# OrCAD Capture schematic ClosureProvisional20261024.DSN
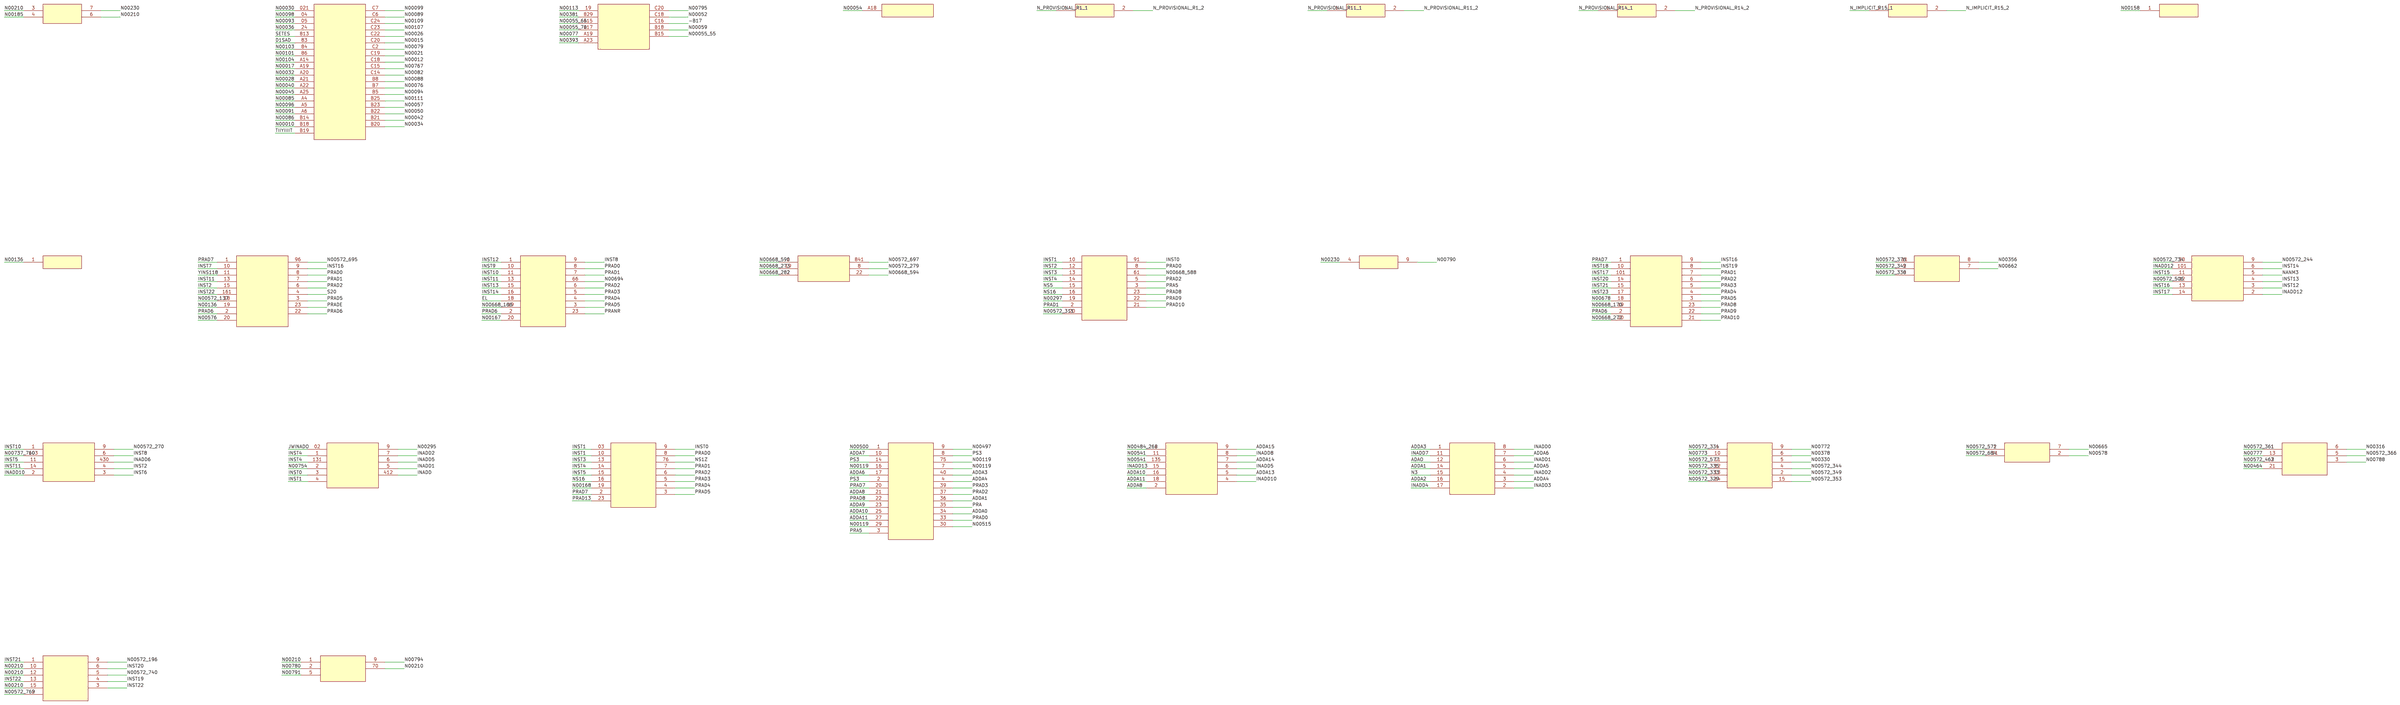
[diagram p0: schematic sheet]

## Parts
J1  CONNECTOR
P1  CONNECTOR
P2  CONNECTOR
P3  CONNECTOR
R1  1K00
R11  1K00
R14  1K00
R15  1K00
R18  330R
R20  510R
U1  UNKNOWN
U2  UNKNOWN
U3  UNKNOWN
U13  UNKNOWN
U14  UNKNOWN
U15  UNKNOWN
U19  74F02
U25  74F240
U27  74F174
U28  74F174
U29  74F174
U31  AM291C
U33  74F240
U34  74F240
U38  74F151
U39  74F00
U40  74F103
U_1  74F174
U_2  74F00

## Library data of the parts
J1 = OBS_J1
P1 = OBS_P1
P2 = OBS_P2
P3 = OBS_P3
R1 = OBS_R1
R11 = OBS_R11
R14 = OBS_R14
R15 = OBS_R15
R18 = OBS_R18
R20 = OBS_R20
U1 = OBS_U1
U2 = OBS_U2
U3 = OBS_U3
U13 = OBS_U13
U14 = OBS_U14
U15 = OBS_U15
U19 = OBS_U19
U25 = OBS_U25
U27 = OBS_U27
U28 = OBS_U28
U29 = OBS_U29
U31 = OBS_U31
U33 = OBS_U33
U34 = OBS_U34
U38 = OBS_U38
U39 = OBS_U39
U40 = OBS_U40
U_1 = OBS_U_1
U_2 = OBS_U_2

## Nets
-B17: P2.C16
ADAO: U34.12
ADDA0: U31.34
ADDA1: U31.36 U34.14
ADDA2: U34.16
ADDA3: U31.40 U34.1
ADDA4: U31.4 U34.3
ADDA5: U34.5
ADDA6: U31.17 U34.7
ADDA7: U31.10
ADDA8: U31.21 U33.2
ADDA9: U31.23
ADDA10: U31.25 U33.16
ADDA11: U31.27 U33.18
ADDA13: U33.5
ADDA14: U33.7
ADDA15: U33.9
D1SAD: P1.83
EL: U13.18
INADD: U29.412
INADD0: U34.8
INADD1: U29.5 U34.6
INADD2: U29.7 U34.4
INADD3: U34.2
INADD4: U34.17
INADD5: U29.6 U33.6
INADD6: U28.430
INADD7: U34.11
INADD8: U33.8
INADD10: U28.2 U33.4
INADD12: U27.2 U27.101
INADD13: U33.15
INST0: U3.9 U15.91 U29.3
INST1: U3.03 U3.10 U15.10 U29.4
INST2: U1.15 U15.12 U28.4
INST3: U3.13 U15.13
INST4: U3.14 U15.14 U29.1 U29.131
INST5: U3.15 U28.11
INST6: U28.3
INST7: U1.10
INST8: U13.9 U28.6
INST9: U13.10
INST10: U13.11 U28.1
INST11: U1.13 U13.13 U28.14
INST12: U13.1 U27.3
INST13: U13.15 U27.4
INST14: U13.16 U27.6
INST15: U27.11
INST16: U1.9 U2.9 U27.13
INST17: U2.101 U27.14
INST18: U2.10
INST19: U2.8 U_1.4
INST20: U2.14 U_1.6
INST21: U2.15 U_1.1
INST22: U1.161 U_1.3 U_1.13
INST23: U2.17
JWINADO: U29.02
N3: U34.15
N00055_55: P2.B15
N00055_65: P2.A15
N00055_70: P2.A17
N00484_268: U33.1
N00572_137: U1.18
N00572_196: U_1.9
N00572_244: U27.9
N00572_270: U28.9
N00572_279: U14.8
N00572_311: U15.20
N00572_329: U38.14
N00572_333: U38.13
N00572_334: U38.1
N00572_335: U38.12
N00572_338: U25.6
N00572_342: U25.5
N00572_344: U38.4
N00572_349: U38.2
N00572_353: U38.15
N00572_361: U40.1
N00572_366: U40.5
N00572_376: U25.11
N00572_463: U40.2
N00572_506: U27.12
N00572_572: U39.1
N00572_577: U38.11
N00572_684: U39.11
N00572_695: U1.96
N00572_697: U14.841
N00572_734: U27.10
N00572_740: U_1.5
N00572_769: U_1.2
N00668_166: U13.19
N00668_170: U2.19
N00668_272: U2.20
N00668_273: U14.19
N00668_282: U14.2
N00668_588: U15.61
N00668_590: U14.1
N00668_594: U14.22
N00737_760: U28.103
N_IMPLICIT_R15_1: R15.1
N_IMPLICIT_R15_2: R15.2
N_PROVISIONAL_R1_1: R1.1
N_PROVISIONAL_R1_2: R1.2
N_PROVISIONAL_R11_1: R11.1
N_PROVISIONAL_R11_2: R11.2
N_PROVISIONAL_R14_1: R14.1
N_PROVISIONAL_R14_2: R14.2
NANM3: U27.5
NS1Z: U3.76
NS5: U15.15
NS16: U3.16 U15.16
PRA: U31.35
PRA5: U15.3 U31.3
PRAD0: U1.8 U3.8 U13.8 U15.8 U31.33
PRAD1: U1.7 U2.7 U3.7 U13.7 U15.2
PRAD2: U1.6 U2.6 U3.6 U13.6 U15.5 U31.37
PRAD3: U2.5 U3.5 U13.5 U31.39
PRAD4: U2.4 U3.4 U13.4
PRAD5: U1.3 U2.3 U3.3 U13.3
PRAD6: U1.2 U1.22 U2.2 U13.2
PRAD7: U1.1 U2.1 U3.2 U31.20
PRAD8: U2.23 U15.23 U31.22
PRAD9: U2.22 U15.22
PRAD10: U2.21 U15.21
PRAD13: U3.23
PRADE: U1.23
PRANR: U13.23
PS3: U31.2 U31.8 U31.14
S20: U1.4
SETES: P1.813
TIIYIIIIT: P1.B19
YINS118: U1.11
N00119: U31.7 U31.16 U31.29 U31.75
N00136: R20.1 U1.19
N00210: J1.3 J1.6 U_1.10 U_1.12 U_1.15 U_2.1 U_2.70
N00230: J1.7 U19.4
N00541: U33.11 U33.135

Not connected (* = marked no-connect by the designer): J1 4; P1 04 05 021 24 84 86 A4 A5 A6 A14 A19 A20 A21 A22 A25 B5 B7 B8 B14 B18 B20 B21 B22 B23 B25 C2 C6 C7 C14 C15 C18 C19 C20 C22 C23 C24; P2 19 829 A19 A23 B18 C18 C20; P3 A18; R18 1; U1 20; U2 18; U3 19; U13 20 66; U15 19; U19 9; U25 7 8; U29 2 9; U31 1 9 30; U38 5 6 9 10; U39 2 7; U40 3 6 13 21; U_2 2 5 9
